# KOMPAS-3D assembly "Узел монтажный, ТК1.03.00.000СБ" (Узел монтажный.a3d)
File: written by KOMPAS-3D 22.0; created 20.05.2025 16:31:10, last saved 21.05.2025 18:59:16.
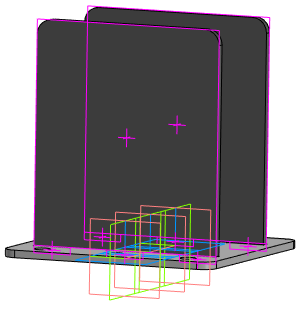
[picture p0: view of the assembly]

Document properties: Автор: TC; Полное имя файла: Узел монтажный _ ТК1.03.00.000 СБ.cdw

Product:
- Component [detail]: Пластина фланцевая  | designation ТК1.03.00.001  | qty 1  | pos. 1  | Масса: 0.815547; Форматы листов документа: A4; source file: Пластина фланцевая _ 5.cdw, Пластина фланцевая.m3d, ТК1.03.00.001 - Пластина фланцевая.cdw
- Component [detail]: Пластина боковая  | designation ТК1.03.00.002  | qty 2  | pos. 2  | Материал: Сталь 09Г2С ГОСТ 19281-2014 (density 7850 kg/m3); Масса: 0.778998; Форматы листов документа: A4; source file: Пластина боковая _5.cdw, Пластина боковая.cdw, Пластина боковая.m3d
- Part/product: Узел монтажный  | designation ТК1.03.00.000СБ
    Масса: 2.373543
    Форматы листов документа: A3

Referenced files in D:\Работа\2025\5. Май\Задание №6 - Тележка для крыши\3Д\Узел монтажный\: Пластина фланцевая.m3d, Пластина боковая.m3d
Referenced files in D:\Рабочая папка\АРХИВ\612\05\Задание №6 - Тележка для крыши\3Д\Узел монтажный\: Пластина боковая.m3d
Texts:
  ТК1.03.00.000
  ТК1.03.00.000 СБ
  ТК1.03.00.001 Пластина фланцевая
  ТК1.03.00.002 Пластина боковая (1)
  ТК1.03.00.002 Пластина боковая (2)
